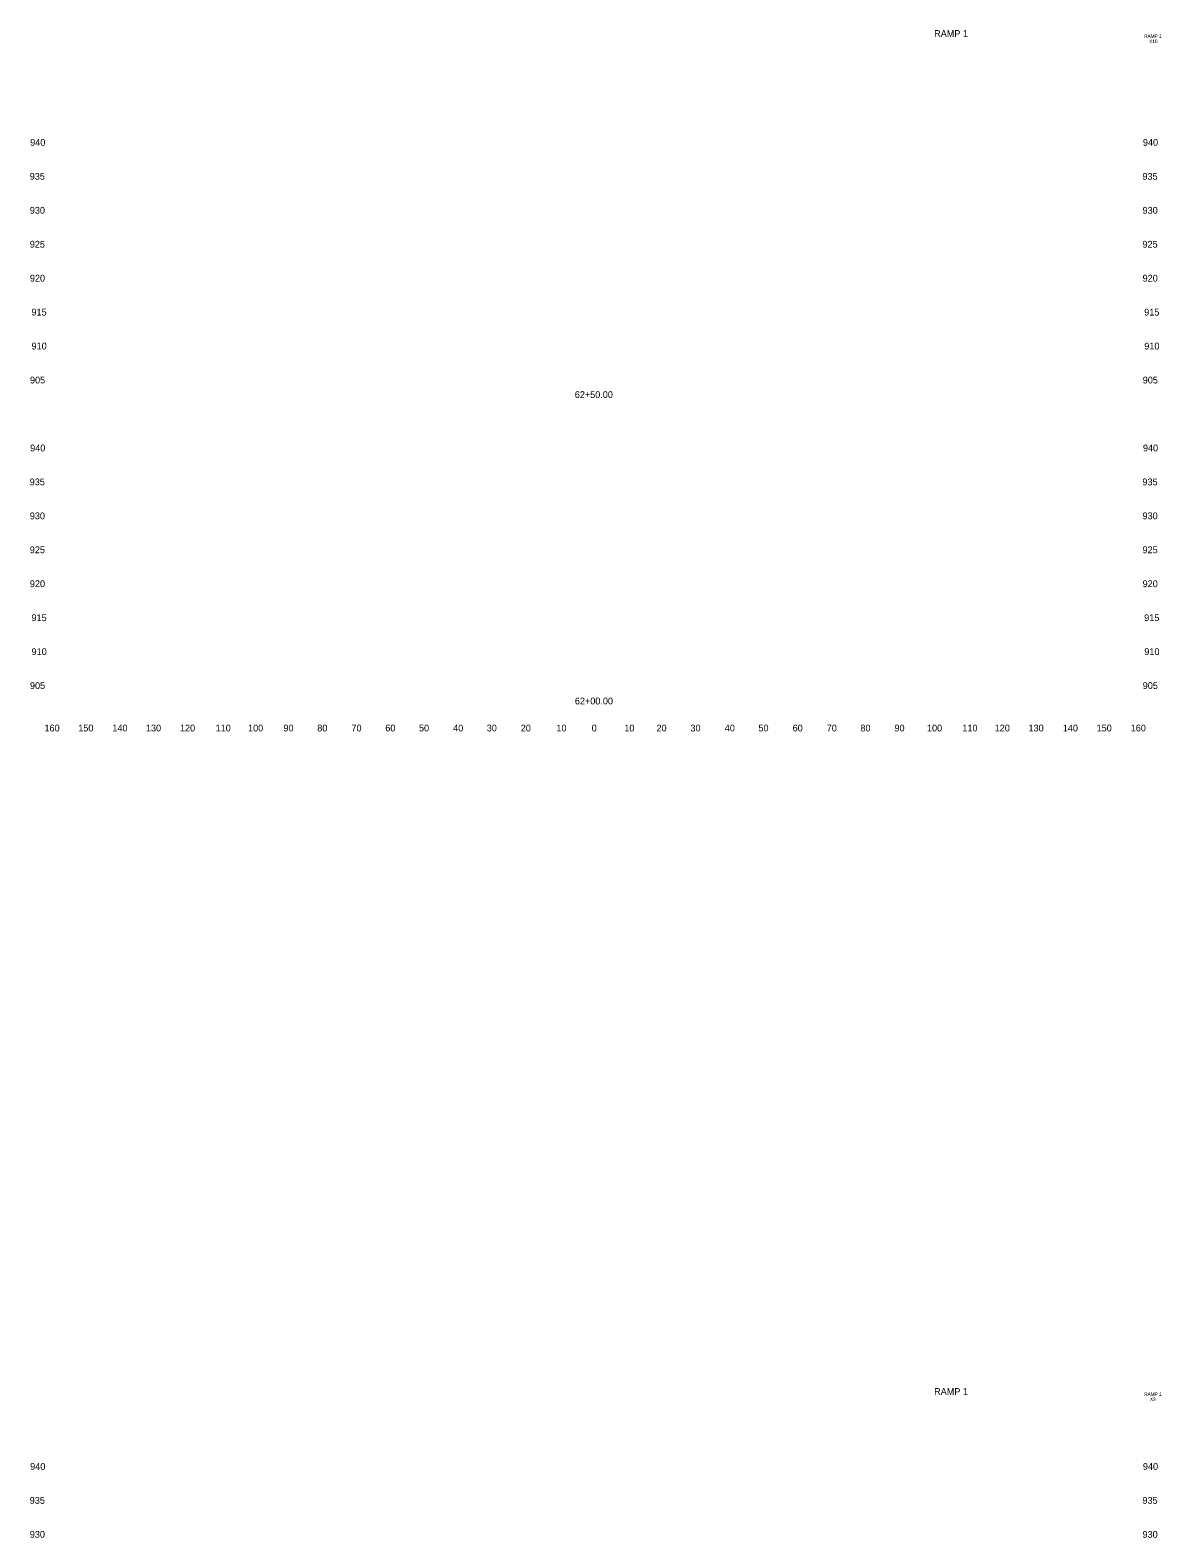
# Model space of a CAD drawing. Extents: x 4994 to 7869, y 4997 to 8804.
# Drawn here: x 4993.9 to 5327, y 8360 to 8804.1 of the extents above; entities that cross this region are included whole.
import ezdxf

# ---------------------------------------------------------------- set-up
doc = ezdxf.new("R2010")
doc.units = 0
for name, color, linetype in [('RD_SHT_ID', 7, 'Continuous'), ('RD_XS_TX_Offset', 7, 'Continuous'), ('RD_XS_TX_Station', 7, 'Continuous')]:
    doc.layers.add(name, color=color, linetype=linetype)

msp = doc.modelspace()

# ---------------------------------------------------------------- texts
at = {"layer": 'RD_SHT_ID'}
for s, height, p in [('RAMP 1', 2, (5260.19, 8802.06)), ('RAMP 1', 1, (5322.06, 8801.8)), ('X10', 1, (5323.53, 8800.3)), ('RAMP 1', 2, (5260.19, 8402.06)), ('RAMP 1', 1, (5322.06, 8401.8)), ('X9', 1, (5323.74, 8400.3))]:
    msp.add_text(s, height=height, dxfattribs=at).set_placement(p)
at = {"layer": 'RD_XS_TX_Offset'}
for s, p in [('940', (4993.89, 8770)), ('940', (5321.69, 8770)), ('935', (4993.75, 8760)), ('935', (5321.55, 8760)), ('930', (4993.78, 8750)), ('930', (5321.58, 8750)), ('925', (4993.77, 8740)), ('925', (5321.57, 8740)), ('920', (4993.8, 8730)), ('920', (5321.6, 8730)), ('915', (4994.27, 8720)), ('915', (5322.07, 8720)), ('910', (4994.3, 8710)), ('910', (5322.1, 8710)), ('905', (4993.83, 8700)), ('905', (5321.63, 8700)), ('940', (4993.89, 8680)), ('940', (5321.69, 8680)), ('935', (4993.75, 8670)), ('935', (5321.55, 8670)), ('930', (4993.78, 8660)), ('930', (5321.58, 8660)), ('925', (4993.77, 8650)), ('925', (5321.57, 8650)), ('920', (4993.8, 8640)), ('920', (5321.6, 8640)), ('915', (4994.27, 8630)), ('915', (5322.07, 8630)), ('910', (4994.3, 8620)), ('910', (5322.1, 8620)), ('905', (4993.83, 8610)), ('905', (5321.63, 8610)), ('160', (4998.1, 8597.5)), ('150', (5008.04, 8597.5)), ('140', (5018.1, 8597.5)), ('130', (5027.99, 8597.5)), ('120', (5038.01, 8597.5)), ('110', (5048.51, 8597.5)), ('100', (5058.07, 8597.5)), ('90', (5068.5, 8597.5)), ('80', (5078.46, 8597.5)), ('70', (5088.54, 8597.5)), ('60', (5098.5, 8597.5)), ('50', (5108.43, 8597.5)), ('40', (5118.5, 8597.5)), ('30', (5128.39, 8597.5)), ('20', (5138.4, 8597.5)), ('10', (5148.91, 8597.5)), ('0', (5159.3, 8597.5)), ('0', (5159.3, 8597.5)), ('10', (5168.91, 8597.5)), ('20', (5178.4, 8597.5)), ('30', (5188.39, 8597.5)), ('40', (5198.5, 8597.5)), ('50', (5208.43, 8597.5)), ('60', (5218.5, 8597.5)), ('70', (5228.54, 8597.5)), ('80', (5238.46, 8597.5)), ('90', (5248.5, 8597.5)), ('100', (5258.07, 8597.5)), ('110', (5268.51, 8597.5)), ('120', (5278.01, 8597.5)), ('130', (5287.99, 8597.5)), ('140', (5298.1, 8597.5)), ('150', (5308.04, 8597.5)), ('160', (5318.1, 8597.5)), ('940', (4993.89, 8380)), ('940', (5321.69, 8380)), ('935', (4993.75, 8370)), ('935', (5321.55, 8370)), ('930', (4993.78, 8360)), ('930', (5321.58, 8360))]:
    msp.add_text(s, height=2, dxfattribs=at).set_placement(p)
at = {"layer": 'RD_XS_TX_Station'}
for s, p in [('62+50.00', (5154.32, 8695.71)), ('62+00.00', (5154.35, 8605.46))]:
    msp.add_text(s, height=2, dxfattribs=at).set_placement(p)

doc.saveas('drawing.dxf')
